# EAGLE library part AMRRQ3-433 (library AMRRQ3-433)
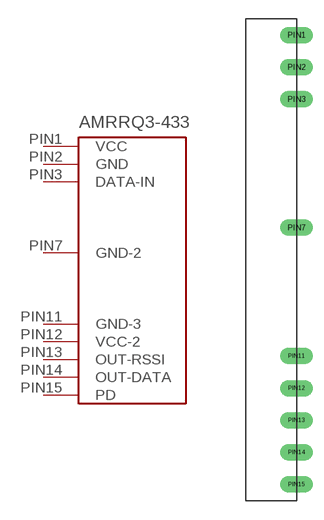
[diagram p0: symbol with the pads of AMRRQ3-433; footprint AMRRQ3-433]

Designator prefix -

## AMRRQ3-433  [AMRRQ3-433]
PIN1  VCC
PIN2  GND
PIN3  DATA-IN
PIN7  GND-2
PIN11  GND-3
PIN12  VCC-2
PIN13  OUT-RSSI
PIN14  OUT-DATA
PIN15  PD

## Footprint AMRRQ3-433 (pad centres in mm)
drill 0.8 long: PIN1 0,17.78; PIN2 0,15.24; PIN3 0,12.7; PIN7 0,2.54; PIN11 0,-7.62; PIN12 0,-10.16; PIN13 0,-12.7; PIN14 0,-15.24; PIN15 0,-17.78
